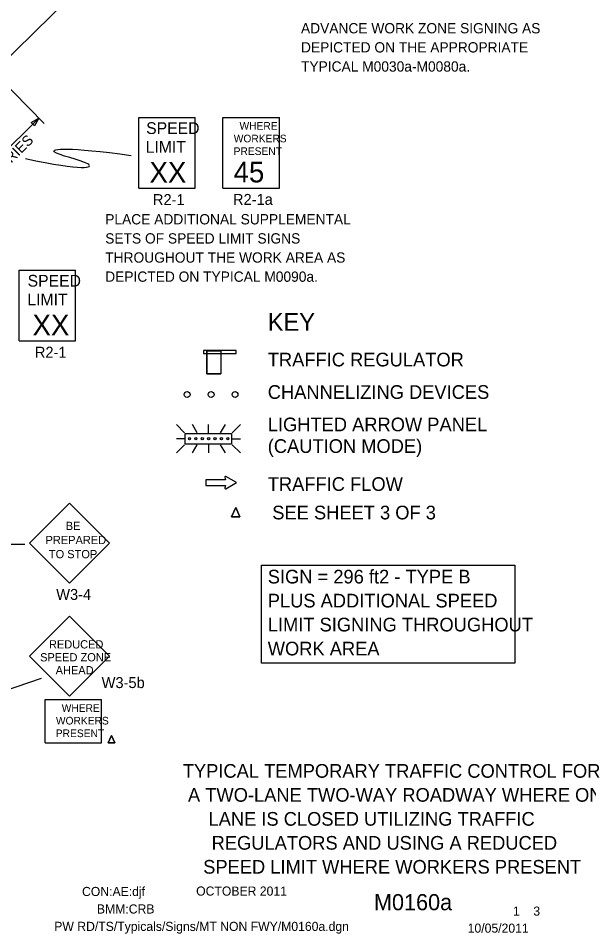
# Model space of a CAD drawing. Extents: x 16735 to 19510, y 5880 to 6929.
# Drawn here: x 17047 to 17435, y 5932 to 6555 of the extents above; entities that cross this region are included whole.
import ezdxf

# ---------------------------------------------------------------- set-up
doc = ezdxf.new("R2010")
doc.units = 0
for name, color, linetype in [('BORDER', 7, 'Continuous'), ('Level 10', 7, 'Continuous'), ('MT_SCRATCH_LEVEL_E', 7, 'Continuous'), ('SCRATCH_LEVEL_A', 7, 'Continuous'), ('TRAFFIC_SIGNS_PR', 7, 'Continuous'), ('TYPICAL_TEXT_DIMEN_EX', 7, 'Continuous')]:
    doc.layers.add(name, color=color, linetype=linetype)

msp = doc.modelspace()

# ---------------------------------------------------------------- linework, layer by layer
at = {"layer": 'BORDER'}
msp.add_line((17374.59, 6855.35), (16953.19, 6442.3), dxfattribs=at)
at = {"layer": 'MT_SCRATCH_LEVEL_E'}
for p, q in [((17187.85, 6242.75), (17188.17, 6240.97)), ((17187.85, 6242.75), (17188.17, 6240.97)), ((17195.78, 6239.12), (17188.54, 6243.23)), ((17195.78, 6239.12), (17188.54, 6243.23)), ((17188.17, 6240.97), (17174.91, 6240.97)), ((17174.91, 6240.97), (17174.91, 6237.23)), ((17188.17, 6240.97), (17174.91, 6240.97)), ((17174.91, 6240.97), (17174.91, 6237.23)), ((17174.91, 6237.23), (17188.17, 6237.23)), ((17174.91, 6237.23), (17188.17, 6237.23)), ((17188.17, 6237.23), (17187.85, 6235.45)), ((17188.17, 6237.23), (17187.85, 6235.45)), ((17188.54, 6234.97), (17195.78, 6239.12)), ((17188.54, 6234.97), (17195.78, 6239.12))]:
    msp.add_line(p, q, dxfattribs=at)
for centre, start, end in [((17188.31, 6242.82), 60.42484, 189.96381), ((17188.31, 6242.82), 60.42484, 189.96381), ((17188.31, 6235.38), 170.03619, 299.77312), ((17188.31, 6235.38), 170.03619, 299.77312)]:
    msp.add_arc(centre, 0.463, start, end, dxfattribs=at)
at = {"layer": 'SCRATCH_LEVEL_A'}
for p, q in [((17129.28, 6487.24), (17167.68, 6487.24)), ((17129.28, 6439.24), (17129.28, 6487.24)), ((17167.68, 6439.24), (17167.68, 6487.24)), ((17186.47, 6487.33), (17224.87, 6487.33)), ((17186.47, 6439.33), (17186.47, 6487.33)), ((17224.87, 6439.33), (17224.87, 6487.33)), ((17129.28, 6439.24), (17167.68, 6439.24)), ((17186.47, 6439.33), (17224.87, 6439.33)), ((17047.92, 6383.46), (17086.32, 6383.46)), ((17047.92, 6335.46), (17047.92, 6383.46)), ((17086.32, 6335.46), (17086.32, 6383.46)), ((17047.92, 6335.46), (17086.32, 6335.46)), ((17175.6, 6328.65), (17175.6, 6313.05)), ((17185.19, 6328.65), (17185.19, 6313.05)), ((17175.6, 6313.05), (17185.19, 6313.05)), ((17154.83, 6278.65), (17160.47, 6273.01)), ((17169.01, 6273.01), (17165.75, 6278.65)), ((17176.64, 6273.01), (17176.64, 6278.65)), ((17184.91, 6273.01), (17188.16, 6278.65)), ((17192.81, 6273.01), (17198.45, 6278.65)), ((17160.47, 6268.95), (17154.83, 6268.95)), ((17163.74, 6268.95), (17163.74, 6268.95)), ((17168.09, 6268.95), (17168.09, 6268.95)), ((17172.44, 6268.95), (17172.44, 6268.95)), ((17176.79, 6268.95), (17176.79, 6268.95)), ((17181.13, 6268.95), (17181.13, 6268.95)), ((17185.48, 6268.95), (17185.48, 6268.95)), ((17189.83, 6268.95), (17189.83, 6268.95)), ((17192.81, 6268.95), (17198.45, 6268.95)), ((17154.83, 6259.25), (17160.47, 6264.88)), ((17165.7, 6259.24), (17168.95, 6264.88)), ((17176.64, 6264.88), (17176.64, 6259.24)), ((17188.21, 6259.24), (17184.96, 6264.88)), ((17192.81, 6264.88), (17198.45, 6259.24)), ((17082.14, 6225.12), (17054.99, 6197.96)), ((17109.3, 6197.96), (17082.14, 6225.12)), ((17054.99, 6197.96), (17082.14, 6170.81)), ((17082.14, 6170.81), (17109.3, 6197.96)), ((17082.14, 6148.22), (17054.99, 6121.07)), ((17109.3, 6121.07), (17082.14, 6148.22)), ((17054.99, 6121.07), (17082.14, 6093.91)), ((17082.14, 6093.91), (17109.3, 6121.07)), ((17065.56, 6091.59), (17103.96, 6091.59)), ((17065.56, 6062.28), (17065.56, 6091.59)), ((17103.96, 6062.28), (17103.96, 6091.59)), ((17065.56, 6062.28), (17103.96, 6062.28))]:
    msp.add_line(p, q, dxfattribs=at)
for points in [[(17195.6, 6328.98), (17173.22, 6328.98), (17173.22, 6326.88), (17195.6, 6326.88)], [(17175.6, 6328.65), (17185.19, 6328.65), (17185.19, 6313.05), (17175.6, 6313.05)], [(17192.35, 6265.35), (17160.93, 6265.35), (17160.93, 6272.55), (17192.35, 6272.55)]]:
    msp.add_lwpolyline(points, close=True, dxfattribs=at)
for points in [[(17195.19, 6222.12), (17192.39, 6215.95)], [(17192.39, 6215.95), (17195.19, 6222.12)], [(17197.98, 6215.95), (17195.19, 6222.12)], [(17195.19, 6222.12), (17197.98, 6215.95)], [(17192.39, 6215.95), (17197.98, 6215.95)], [(17197.98, 6215.95), (17192.39, 6215.95)], [(17110.7, 6067.22), (17108.47, 6062.28)], [(17108.47, 6062.28), (17110.7, 6067.22)], [(17108.47, 6062.28), (17112.94, 6062.28)], [(17112.94, 6062.28), (17108.47, 6062.28)], [(17112.94, 6062.28), (17110.7, 6067.22)], [(17110.7, 6067.22), (17112.94, 6062.28)]]:
    msp.add_lwpolyline(points, dxfattribs=at)
for centre, radius in [((17162.15, 6298.98), 2), ((17178.45, 6298.98), 2), ((17194.75, 6298.98), 2), ((17163.78, 6268.95), 0.758), ((17168.09, 6268.95), 0.758), ((17172.44, 6268.95), 0.758), ((17176.79, 6268.95), 0.758), ((17181.13, 6268.95), 0.758), ((17185.48, 6268.95), 0.758), ((17189.83, 6268.95), 0.758)]:
    msp.add_circle(centre, radius, dxfattribs=at)
at = {"layer": 'TRAFFIC_SIGNS_PR'}
for p, q in [((17064.92, 6483.21), (17021.73, 6527.27)), ((17061.42, 6486.78), (17031.97, 6457.92)), ((17056.14, 6483.8), (17061.42, 6486.78)), ((17061.42, 6486.78), (17058.34, 6481.56)), ((17057.24, 6482.68), (17056.14, 6483.8)), ((17058.34, 6481.56), (17057.24, 6482.68)), ((16940.83, 6197.3), (17051.85, 6197.3)), ((17037.22, 6097.3), (17063.1, 6106.27))]:
    msp.add_line(p, q, dxfattribs=at)
msp.add_open_spline([(17052.26, 6459.39), (17092.12, 6450.8), (17105.97, 6455.31), (17058.23, 6464.89), (17080.87, 6467.49), (17124.13, 6461.51)], degree=3, dxfattribs=at)
at = {"layer": 'TYPICAL_TEXT_DIMEN_EX'}
msp.add_lwpolyline([(17212.8, 6182.98), (17385.09, 6182.98), (17385.09, 6116.26), (17212.8, 6116.26)], close=True, dxfattribs=at)

# ---------------------------------------------------------------- texts
at = {"layer": 'Level 10'}
for s, height, p in [('TYPICAL TEMPORARY TRAFFIC CONTROL FOR', 9.3, (17159.21, 6038.47)), ('A TWO-LANE TWO-WAY ROADWAY WHERE ONE', 9.3, (17162.73, 6022.17)), ('LANE IS CLOSED UTILIZING TRAFFIC', 9.3, (17176.71, 6005.87)), ('  REGULATORS AND USING A REDUCED ', 9.3, (17171.92, 5989.57)), ('SPEED LIMIT WHERE WORKERS PRESENT', 9.3, (17173.08, 5973.27)), ('CON:AE:djf', 6.2, (17090.69, 5958.06)), ('    OCTOBER 2011    ', 6.2, (17159.08, 5958.34)), ('    M0160a   ', 11, (17272.86, 5948.38)), ('BMM:CRB   ', 6.2, (17100.81, 5946.17)), (' 1    3 ', 6.2, (17381.45, 5944.7)), ('PW RD/TS/Typicals/Signs/MT NON FWY/M0160a.dgn    ', 6.2, (17071.79, 5934.33)), ('10/05/2011    ', 6.2, (17352.93, 5933.13))]:
    msp.add_text(s, height=height, dxfattribs=at).set_placement(p)
at = {"layer": 'SCRATCH_LEVEL_A'}
for s, height, p in [('ADVANCE WORK ZONE SIGNING AS', 7, (17239.59, 6544.5)), ('DEPICTED ON THE APPROPRIATE', 7, (17239.59, 6531.5)), ('TYPICAL M0030a-M0080a.', 7, (17239.59, 6518.5)), ('SPEED', 8, (17134.31, 6476.1)), ('WHERE', 5.2, (17197.78, 6479.02)), ('WORKERS', 5.2, (17193.86, 6470.42)), ('LIMIT', 8, (17133.98, 6463.3)), ('PRESENT', 5.2, (17193.79, 6461.82)), ('XX', 14.031, (17136.58, 6443)), ('45', 14.031, (17193.78, 6443.19)), ('R2-1', 7.44, (17138.89, 6427.8)), ('R2-1a', 7.44, (17193.33, 6427.89)), ('PLACE ADDITIONAL SUPPLEMENTAL', 7, (17106.47, 6414.63)), ('SETS OF SPEED LIMIT SIGNS', 7, (17106.47, 6401.63)), ('THROUGHOUT THE WORK AREA AS', 7, (17106.47, 6388.63)), ('SPEED', 8, (17053.69, 6372.33)), ('DEPICTED ON TYPICAL M0090a.', 7, (17106.47, 6375.63)), ('LIMIT', 8, (17053.52, 6359.53)), ('XX', 14.031, (17057.03, 6339.22)), ('R2-1', 7.44, (17058.6, 6324.02)), ('BE', 5.6, (17079.64, 6206.89)), ('PREPARED', 5.6, (17065.89, 6197.29)), ('TO STOP', 5.6, (17068.17, 6187.69)), ('W3-4', 7.44, (17073.15, 6159.37)), ('REDUCED', 5.6, (17068.2, 6126.37)), ('SPEED ZONE', 5.6, (17062.19, 6117.57)), ('AHEAD', 5.6, (17072.75, 6108.77)), ('W3-5b', 7.44, (17104.02, 6099.43)), ('WHERE', 5.2, (17076.87, 6083.28)), ('WORKERS', 5.2, (17072.94, 6074.68)), ('PRESENT', 5.2, (17072.87, 6066.08))]:
    msp.add_text(s, height=height, dxfattribs=at).set_placement(p)
at = {"layer": 'TRAFFIC_SIGNS_PR'}
msp.add_text('VARIES', height=7, rotation=44.42594, dxfattribs=at).set_placement((17033.67, 6447.21))
at = {"layer": 'TYPICAL_TEXT_DIMEN_EX'}
for s, height, p in [('KEY', 12, (17216.99, 6342.3)), ('TRAFFIC REGULATOR', 9.3, (17216.99, 6318.09)), ('CHANNELIZING DEVICES', 9.3, (17216.99, 6296.04)), ('LIGHTED ARROW PANEL', 9.3, (17216.99, 6273.99)), ('(CAUTION MODE)', 9.3, (17216.99, 6259.29)), ('TRAFFIC FLOW', 9.3, (17216.99, 6233.49)), ('SEE SHEET 3 OF 3', 9.3, (17220.05, 6214.11)), ('SIGN = 296 ft2 - TYPE B', 9.3, (17216.99, 6170.53)), ('PLUS ADDITIONAL SPEED', 9.3, (17216.99, 6154.23)), ('LIMIT SIGNING THROUGHOUT', 9.3, (17216.99, 6137.93)), ('WORK AREA', 9.3, (17216.99, 6121.63))]:
    msp.add_text(s, height=height, dxfattribs=at).set_placement(p)

doc.saveas('drawing.dxf')
